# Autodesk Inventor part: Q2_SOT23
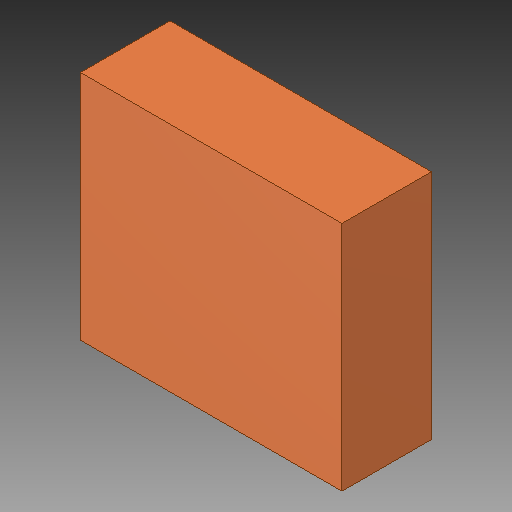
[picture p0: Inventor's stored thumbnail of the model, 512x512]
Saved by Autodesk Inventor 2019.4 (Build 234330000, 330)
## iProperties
Created: 2019-11
Part Number: Q2_SOT23
Material: Generic
Document SubType Name: Modeling
Designer: Willist
Density: 1 g/cm^3
Appearance: SOT23, Q2_SOT23
Author: Willist
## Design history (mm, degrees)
sketch "SOT23, Q2_SOT23_75"
  geometry: L1 (-1.422, 1.295)-(1.499, 1.295); L2 (1.499, 1.295)-(1.499, -1.295); L3 (1.499, -1.295)-(-1.422, -1.295); L4 (-1.422, -1.295)-(-1.422, 1.295)
  constraints: 8 end point
extrude "Extrusion1" join sketch "SOT23, Q2_SOT23_75" distance "d0" = 1; taper "d1" = 0 deg
body "Solid1"
